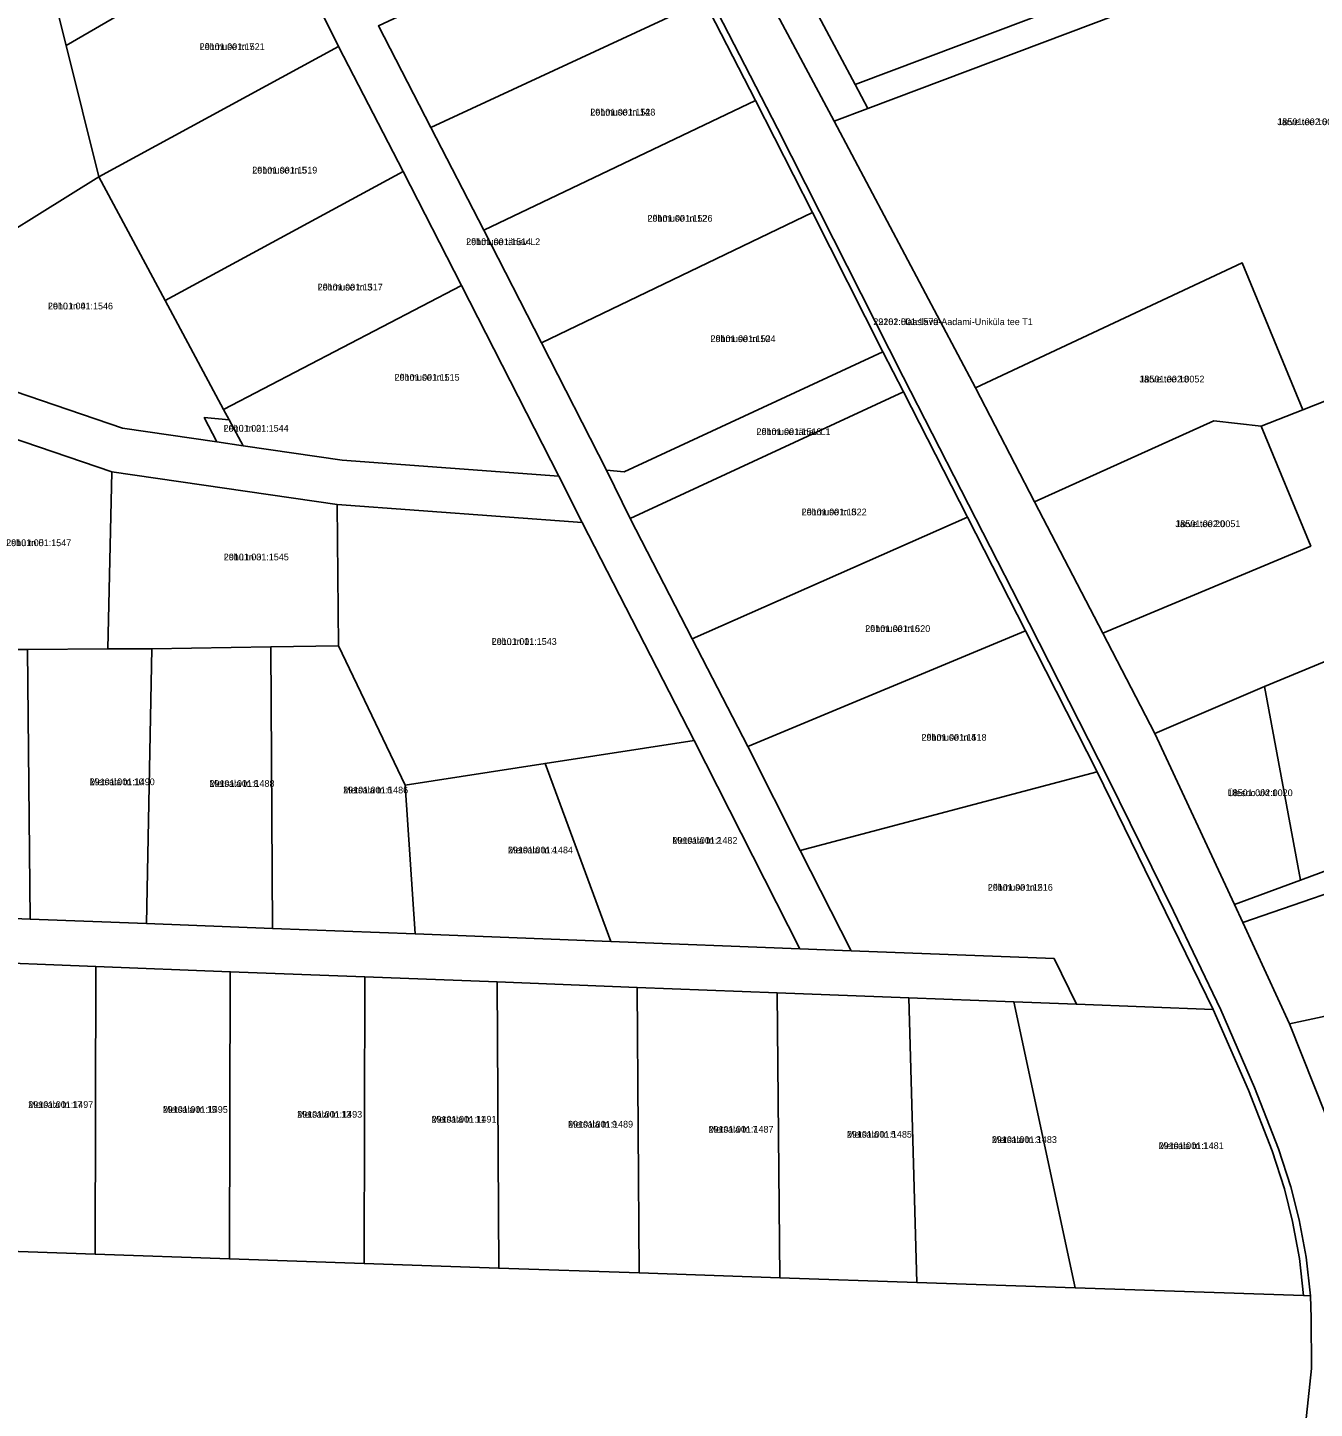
# Model space of a CAD drawing. Extents: x 660838 to 697091, y 6455678 to 6479886.
# Drawn here: x 664844.9 to 665132, y 6467450.2 to 6467758.1 of the extents above; entities that cross this region are included whole.
import ezdxf

# ---------------------------------------------------------------- set-up
doc = ezdxf.new("R2010")
doc.units = 0
for name, color, linetype in [('L_AADRESS', 7, 'Continuous'), ('PIIR', 7, 'Continuous'), ('TUNNUS', 7, 'Continuous')]:
    doc.layers.add(name, color=color, linetype=linetype)

msp = doc.modelspace()

# ---------------------------------------------------------------- linework, layer by layer
at = {"layer": 'PIIR'}
for points in [[(664960.59, 6467884.87), (664968.02, 6467887.96), (664979.36, 6467840.03), (665008.57, 6467784.79), (665029.52, 6467745.44), (665032.37, 6467740.11), (665024.83, 6467737.25), (665000.57, 6467782.66), (664971.81, 6467837.2)], [(664842.36, 6467851.27), (664867.78, 6467863.95), (664869.83, 6467846.19), (664877, 6467822.84), (664860.47, 6467801.99), (664847.14, 6467779.64), (664853.5, 6467754.14), (664860.79, 6467724.82), (664827.31, 6467704.02), (664819.37, 6467690.3), (664799.08, 6467717.91), (664813.14, 6467745.61), (664804.89, 6467786.54), (664808.03, 6467816.03), (664815.87, 6467838.1)], [(665076.38, 6467862.33), (665076.82, 6467861.19), (665110.11, 6467769.49), (665032.37, 6467740.11), (665029.52, 6467745.44), (665083.88, 6467765.99), (665068.77, 6467807.59), (665081.9, 6467812.56)], [(664860.47, 6467801.99), (664877, 6467822.84), (664891.19, 6467802.11), (664900.62, 6467781.47), (664853.5, 6467754.14), (664847.14, 6467779.64)], [(665008.57, 6467784.79), (665068.77, 6467807.59), (665083.88, 6467765.99), (665029.52, 6467745.44)], [(664934.86, 6467735.87), (664923.19, 6467758.51), (664984.05, 6467786.92), (664995.82, 6467764.09)], [(664853.5, 6467754.14), (664900.62, 6467781.47), (664914.29, 6467753.92), (664860.79, 6467724.82)], [(664934.86, 6467735.87), (664995.82, 6467764.09), (665007.3, 6467741.85), (664946.71, 6467712.94)], [(664860.79, 6467724.82), (664914.29, 6467753.92), (664928.7, 6467726.05), (664875.61, 6467697.26)], [(664946.71, 6467712.94), (665007.3, 6467741.85), (665019.99, 6467716.91), (664959.55, 6467687.84)], [(664875.61, 6467697.26), (664928.7, 6467726.05), (664941.72, 6467700.64), (664888.65, 6467672.94)], [(664829.88, 6467681.16), (664819.37, 6467690.3), (664827.31, 6467704.02), (664860.79, 6467724.82), (664875.61, 6467697.26), (664888.65, 6467672.94), (664889.91, 6467670.66), (664884.33, 6467671.17), (664887.16, 6467665.73), (664866.07, 6467668.81)], [(664974.06, 6467659.41), (664959.55, 6467687.84), (665019.99, 6467716.91), (665035.73, 6467685.85), (664978, 6467659.08)], [(665056.35, 6467677.76), (665115.86, 6467705.64), (665129.42, 6467672.9), (665120.12, 6467669.23), (665109.51, 6467670.4), (665069.56, 6467652.33)], [(664888.65, 6467672.94), (664941.72, 6467700.64), (664963.43, 6467658.12), (664915.06, 6467661.69), (664893.02, 6467664.87), (664889.91, 6467670.66)], [(664978, 6467659.08), (665035.73, 6467685.85), (665040.29, 6467676.92), (664979.32, 6467648.65), (664974.06, 6467659.41)], [(665054.59, 6467648.91), (664993.18, 6467621.79), (664979.32, 6467648.65), (665040.29, 6467676.92)], [(664893.02, 6467664.87), (664887.16, 6467665.73), (664884.33, 6467671.17), (664889.91, 6467670.66)], [(665069.56, 6467652.33), (665109.51, 6467670.4), (665120.12, 6467669.23), (665131.17, 6467642.51), (665084.77, 6467623.04)], [(664816.61, 6467619.42), (664840.82, 6467666.85), (664863.68, 6467659.07), (664862.83, 6467619.55), (664844.92, 6467619.44)], [(664862.83, 6467619.55), (664863.68, 6467659.07), (664914, 6467651.74), (664914.26, 6467620.22), (664899.2, 6467620.01), (664872.62, 6467619.6)], [(664914.26, 6467620.22), (664914, 6467651.74), (664968.63, 6467647.76), (664993.58, 6467599.14), (664960.34, 6467594.01), (664929.14, 6467589.18)], [(664993.18, 6467621.79), (665054.59, 6467648.91), (665067.5, 6467623.6), (665005.55, 6467597.76)], [(665017.22, 6467574.56), (665005.55, 6467597.76), (665067.5, 6467623.6), (665083.48, 6467592.13)], [(664815.52, 6467560.47), (664816.61, 6467619.42), (664844.92, 6467619.44), (664845.51, 6467559.31)], [(664845.51, 6467559.31), (664844.92, 6467619.44), (664862.83, 6467619.55), (664872.62, 6467619.6), (664871.41, 6467558.32)], [(664872.62, 6467619.6), (664899.2, 6467620.01), (664899.55, 6467557.2), (664871.41, 6467558.32)], [(664899.55, 6467557.2), (664899.2, 6467620.01), (664914.26, 6467620.22), (664929.14, 6467589.18), (664931.39, 6467555.99)], [(665128.84, 6467567.98), (665120.87, 6467611.19), (665136.3, 6467617.56), (665144.11, 6467573.6)], [(665114.12, 6467562.57), (665096.39, 6467600.67), (665120.87, 6467611.19), (665128.84, 6467567.98)], [(664974.99, 6467554.31), (664960.34, 6467594.01), (664993.58, 6467599.14), (665017.16, 6467552.69)], [(664929.14, 6467589.18), (664960.34, 6467594.01), (664974.99, 6467554.31), (664931.39, 6467555.99)], [(665017.22, 6467574.56), (665083.48, 6467592.13), (665109.41, 6467539.1), (665078.88, 6467540.3), (665073.9, 6467550.5), (665028.6, 6467552.23)], [(665126.4, 6467535.93), (665116.01, 6467558.56), (665149.27, 6467570), (665154.83, 6467542.04)], [(664830.13, 6467549.9), (664860.11, 6467548.72), (664860, 6467484.52), (664830.01, 6467485.58)], [(664860, 6467484.52), (664860.11, 6467548.72), (664890.13, 6467547.56), (664889.96, 6467483.53)], [(664890.13, 6467547.56), (664920.13, 6467546.41), (664920.02, 6467482.51), (664889.96, 6467483.53)], [(664920.02, 6467482.51), (664920.13, 6467546.41), (664949.63, 6467545.28), (664950.02, 6467481.43)], [(664949.63, 6467545.28), (664980.89, 6467544.06), (664981.33, 6467480.39), (664950.02, 6467481.43)], [(664981.33, 6467480.39), (664980.89, 6467544.06), (665012.11, 6467542.87), (665012.72, 6467479.31)], [(665012.11, 6467542.87), (665041.46, 6467541.75), (665043.26, 6467478.27), (665012.72, 6467479.31)], [(665043.26, 6467478.27), (665041.46, 6467541.75), (665064.9, 6467540.85), (665078.57, 6467477.05)], [(665137.27, 6467508.61), (665126.4, 6467535.93), (665154.83, 6467542.04), (665155.36, 6467540.12), (665158.02, 6467526.12), (665158.69, 6467509.87)], [(665078.88, 6467540.3), (665109.41, 6467539.1), (665117.26, 6467521.16), (665122.55, 6467507.6), (665125.27, 6467499.12), (665127.09, 6467491.87), (665128.61, 6467483.61), (665129.57, 6467475.3), (665078.57, 6467477.05), (665064.9, 6467540.85)]]:
    msp.add_lwpolyline(points, close=True, dxfattribs=at)
for points in [[(665048.64, 6467181.37), (665065.29, 6467240.78), (665085.51, 6467304.71), (665123.89, 6467417.89), (665129.45, 6467441.55), (665131.29, 6467459.05), (665131.23, 6467470.35), (665131.11, 6467475.24), (665130.1, 6467483.85), (665128.58, 6467492.21), (665126.72, 6467499.55), (665123.99, 6467508.07), (665118.63, 6467521.76), (665111.11, 6467539.07), (665100.51, 6467561.03), (665086.01, 6467590.52), (665066.11, 6467629.68), (665040.26, 6467680.23), (665012.21, 6467735.6), (664980.64, 6467796.8)], [(664980.64, 6467796.8), (665012.21, 6467735.6), (665040.26, 6467680.23), (665066.11, 6467629.68), (665086.01, 6467590.52), (665100.51, 6467561.03), (665111.11, 6467539.07), (665118.63, 6467521.76), (665123.99, 6467508.07), (665126.72, 6467499.55), (665128.58, 6467492.21), (665130.1, 6467483.85), (665131.11, 6467475.24), (665129.57, 6467475.3), (665128.61, 6467483.61), (665127.09, 6467491.87), (665125.27, 6467499.12), (665122.55, 6467507.6), (665117.26, 6467521.16), (665109.41, 6467539.1), (665083.48, 6467592.13), (665067.5, 6467623.6), (665054.59, 6467648.91), (665040.29, 6467676.92), (665035.73, 6467685.85), (665019.99, 6467716.91), (665007.3, 6467741.85), (664995.82, 6467764.09)], [(664923.19, 6467758.51), (664934.86, 6467735.87), (664946.71, 6467712.94), (664959.55, 6467687.84), (664974.06, 6467659.41), (664979.32, 6467648.65), (664993.18, 6467621.79), (665005.55, 6467597.76), (665017.22, 6467574.56), (665028.6, 6467552.23), (665017.16, 6467552.69), (664993.58, 6467599.14), (664968.63, 6467647.76), (664963.43, 6467658.12), (664941.72, 6467700.64), (664928.7, 6467726.05), (664914.29, 6467753.92), (664900.62, 6467781.47)], [(665000.57, 6467782.66), (665024.83, 6467737.25), (665056.35, 6467677.76), (665069.56, 6467652.33), (665084.77, 6467623.04), (665096.39, 6467600.67), (665114.12, 6467562.57), (665116.01, 6467558.56), (665126.4, 6467535.93), (665137.27, 6467508.61), (665138.8, 6467504.68), (665144.23, 6467470.51), (665144.3, 6467458.27), (665142.2, 6467439.35), (665136.57, 6467415.04), (665097.48, 6467299.63), (665077.59, 6467236.57), (665061.23, 6467178.15)], [(665209.85, 6467759.39), (665209.85, 6467756.74), (665211.78, 6467754.87), (665214.31, 6467754.69), (665217.15, 6467752.88), (665218.9, 6467748.78), (665219.88, 6467745.51), (665220.64, 6467742.99), (665222.69, 6467733.65), (665223.19, 6467729.31), (665224.48, 6467724.51), (665226.25, 6467723.63), (665227.7, 6467721.52), (665228.3, 6467718.2), (665228.24, 6467715.37), (665228.52, 6467711.98), (665223.43, 6467709.97), (665129.42, 6467672.9), (665115.86, 6467705.64), (665056.35, 6467677.76), (665024.83, 6467737.25), (665032.37, 6467740.11), (665110.11, 6467769.49)], [(665136.3, 6467617.56), (665120.87, 6467611.19), (665096.39, 6467600.67), (665084.77, 6467623.04), (665131.17, 6467642.51), (665120.12, 6467669.23), (665129.42, 6467672.9), (665223.43, 6467709.97)], [(664829.88, 6467681.16), (664866.07, 6467668.81), (664887.16, 6467665.73), (664893.02, 6467664.87), (664915.06, 6467661.69), (664963.43, 6467658.12), (664968.63, 6467647.76), (664914, 6467651.74), (664863.68, 6467659.07), (664840.82, 6467666.85)], [(665149.27, 6467570), (665116.01, 6467558.56), (665114.12, 6467562.57), (665128.84, 6467567.98), (665144.11, 6467573.6)], [(664815.52, 6467560.47), (664845.51, 6467559.31), (664871.41, 6467558.32), (664899.55, 6467557.2), (664931.39, 6467555.99), (664974.99, 6467554.31), (665017.16, 6467552.69), (665028.6, 6467552.23), (665073.9, 6467550.5), (665078.88, 6467540.3), (665064.9, 6467540.85), (665041.46, 6467541.75), (665012.11, 6467542.87), (664980.89, 6467544.06), (664949.63, 6467545.28), (664920.13, 6467546.41), (664890.13, 6467547.56), (664860.11, 6467548.72), (664830.13, 6467549.9)], [(664830.01, 6467485.58), (664860, 6467484.52), (664889.96, 6467483.53), (664920.02, 6467482.51), (664950.02, 6467481.43), (664981.33, 6467480.39), (665012.72, 6467479.31), (665043.26, 6467478.27), (665078.57, 6467477.05), (665129.57, 6467475.3), (665131.11, 6467475.24), (665131.23, 6467470.35), (665131.29, 6467459.05), (665129.45, 6467441.55), (665123.89, 6467417.89), (665085.51, 6467304.71), (665065.29, 6467240.78), (665048.64, 6467181.37)]]:
    msp.add_lwpolyline(points, dxfattribs=at)

# ---------------------------------------------------------------- texts
at = {"layer": 'L_AADRESS'}
for s, p in [('Lõhmuse tn 7', (664883.31, 6467753.15)), ('Lõhmuse tn 14', (664970.44, 6467738.52)), ('Järve tee 16', (665123.69, 6467736.38)), ('Lõhmuse tn 5', (664895.03, 6467725.59)), ('Lõhmuse tn 12', (664983.2, 6467714.85)), ('Lõhmuse tänav L2', (664942.75, 6467709.62)), ('Lõhmuse tn 3', (664909.63, 6467699.5)), ('Lohu tn 4', (664849.46, 6467695.28)), ('22262 Haaslava-Aadami-Uniküla tee T1', (665033.57, 6467691.78)), ('Lõhmuse tn 10', (664997.26, 6467687.99)), ('Lõhmuse tn 1', (664926.78, 6467679.38)), ('Järve tee 18', (665092.93, 6467678.99)), ('Lohu tn 2', (664888.65, 6467668.02)), ('Lõhmuse tänav L1', (665007.53, 6467667.25)), ('Lõhmuse tn 8', (665017.6, 6467649.36)), ('Järve tee 20', (665100.95, 6467646.72)), ('Lohu tn 5', (664840.14, 6467642.48)), ('Lohu tn 3', (664888.68, 6467639.31)), ('Lõhmuse tn 6', (665031.77, 6467623.34)), ('Lohu tn 1', (664948.45, 6467620.46)), ('Lõhmuse tn 4', (665044.33, 6467599.08)), ('Metsala tn 10', (664858.77, 6467589.16)), ('Metsala tn 8', (664885.48, 6467588.78)), ('Metsala tn 6', (664915.3, 6467587.33)), ('Ülesoo vkt 1', (665112.62, 6467586.72)), ('Metsala tn 4', (664952.07, 6467573.96)), ('Metsala tn 2', (664988.75, 6467576.09)), ('Lõhmuse tn 2', (665059.11, 6467565.62)), ('Metsala tn 17', (664845.06, 6467517.18)), ('Metsala tn 15', (664875.07, 6467516.08)), ('Metsala tn 13', (664905.05, 6467515)), ('Metsala tn 11', (664935.02, 6467513.9)), ('Metsala tn 9', (664965.48, 6467512.79)), ('Metsala tn 7', (664996.8, 6467511.66)), ('Metsala tn 5', (665027.68, 6467510.54)), ('Metsala tn 3', (665060.02, 6467509.36)), ('Metsala tn 1', (665097.23, 6467507.99))]:
    msp.add_text(s, height=1.5, dxfattribs=at).set_placement(p)
at = {"layer": 'TUNNUS'}
for s, p in [('29101:001:1521', (664883.31, 6467753.15)), ('29101:001:1528', (664970.44, 6467738.52)), ('18501:002:0041', (665123.69, 6467736.38)), ('29101:001:1519', (664895.03, 6467725.59)), ('29101:001:1526', (664983.2, 6467714.85)), ('29101:001:1514', (664942.75, 6467709.62)), ('29101:001:1517', (664909.63, 6467699.5)), ('29101:001:1546', (664849.46, 6467695.28)), ('29101:001:1570', (665033.57, 6467691.78)), ('29101:001:1524', (664997.26, 6467687.99)), ('29101:001:1515', (664926.78, 6467679.38)), ('18501:002:0052', (665092.93, 6467678.99)), ('29101:001:1544', (664888.65, 6467668.02)), ('29101:001:1513', (665007.53, 6467667.25)), ('29101:001:1522', (665017.6, 6467649.36)), ('18501:002:0051', (665100.95, 6467646.72)), ('29101:001:1547', (664840.14, 6467642.48)), ('29101:001:1545', (664888.68, 6467639.31)), ('29101:001:1520', (665031.77, 6467623.34)), ('29101:001:1543', (664948.45, 6467620.46)), ('29101:001:1518', (665044.33, 6467599.08)), ('29101:001:1490', (664858.77, 6467589.16)), ('29101:001:1488', (664885.48, 6467588.78)), ('29101:001:1486', (664915.3, 6467587.33)), ('18501:002:0020', (665112.62, 6467586.72)), ('29101:001:1484', (664952.07, 6467573.96)), ('29101:001:1482', (664988.75, 6467576.09)), ('29101:001:1516', (665059.11, 6467565.62)), ('29101:001:1497', (664845.06, 6467517.18)), ('29101:001:1495', (664875.07, 6467516.08)), ('29101:001:1493', (664905.05, 6467515)), ('29101:001:1491', (664935.02, 6467513.9)), ('29101:001:1489', (664965.48, 6467512.79)), ('29101:001:1487', (664996.8, 6467511.66)), ('29101:001:1485', (665027.68, 6467510.54)), ('29101:001:1483', (665060.02, 6467509.36)), ('29101:001:1481', (665097.23, 6467507.99))]:
    msp.add_text(s, height=1.5, dxfattribs=at).set_placement(p)

doc.saveas('drawing.dxf')
